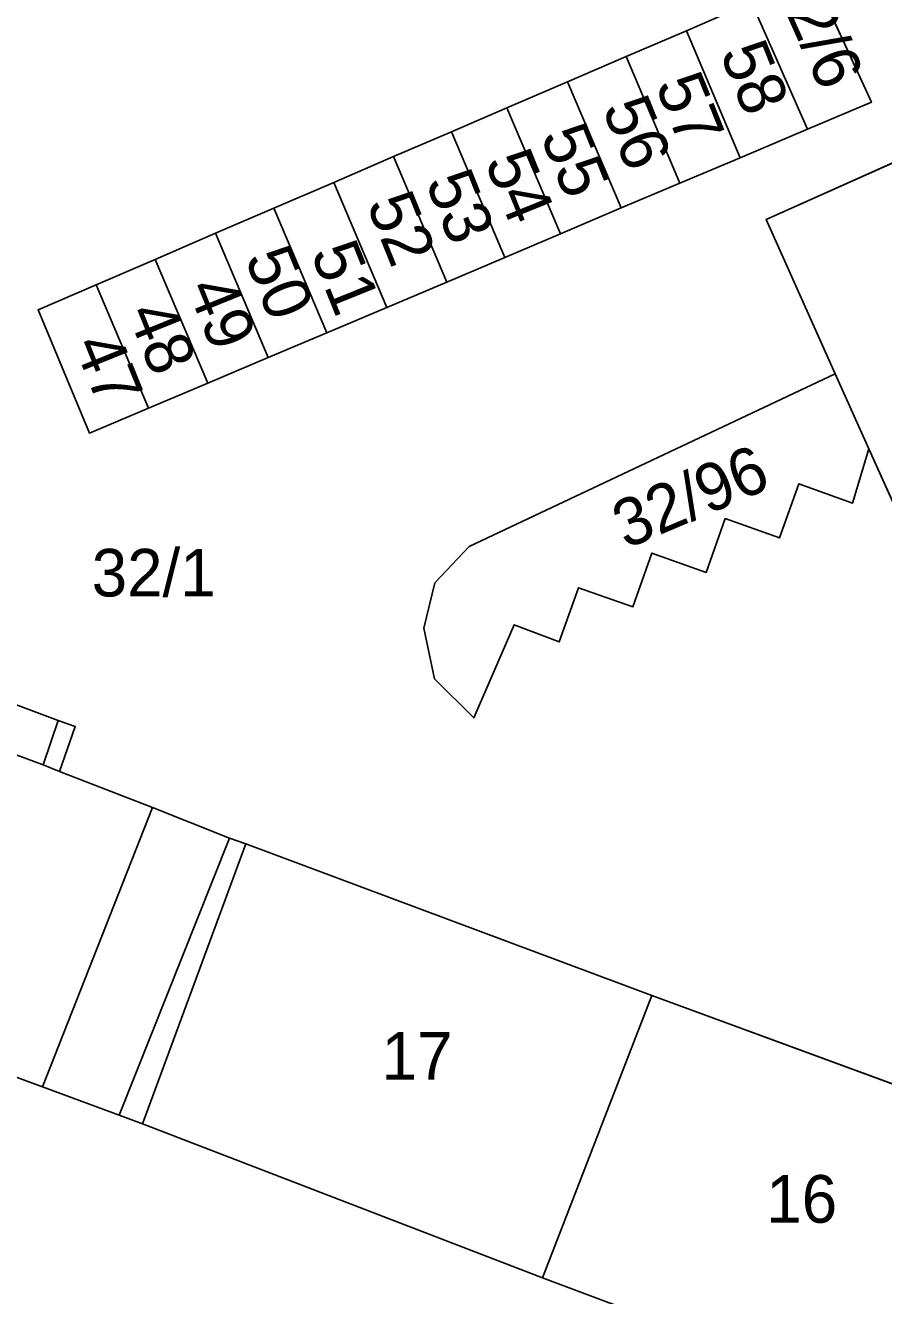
# Model space of a CAD drawing. Extents: x -264070 to -262271, y -1238894 to -1238141.
# Drawn here: x -263478.9 to -263442.9, y -1238836.1 to -1238782.8 of the extents above; entities that cross this region are included whole.
import ezdxf

# ---------------------------------------------------------------- set-up
doc = ezdxf.new("R2010")
doc.units = 0
for name, color, linetype in [('body_kn', 7, 'Continuous'), ('katuz_linie', 7, 'Continuous'), ('kladpar_druhypozemkov', 7, 'Continuous'), ('kladpar_hranice', 7, 'Continuous'), ('kladpar_parcelnecisla', 7, 'Continuous'), ('kladpar_plochy', 7, 'Continuous'), ('zappar_hrandruhpozemk', 7, 'Continuous'), ('zuob_linie', 7, 'Continuous'), ('zuob_plochy', 7, 'Continuous')]:
    doc.layers.add(name, color=color, linetype=linetype)

msp = doc.modelspace()

# ---------------------------------------------------------------- linework, layer by layer
at = {"layer": 'body_kn'}
for p, q in [((-263451.18, -1238783.03), (-263451.18, -1238783.03)), ((-263451.18, -1238783.03), (-263451.18, -1238783.03)), ((-263453.71, -1238784.11), (-263453.71, -1238784.11)), ((-263453.71, -1238784.11), (-263453.71, -1238784.11)), ((-263456.17, -1238785.17), (-263456.17, -1238785.17)), ((-263456.17, -1238785.17), (-263456.17, -1238785.17)), ((-263458.72, -1238786.27), (-263458.72, -1238786.27)), ((-263458.72, -1238786.27), (-263458.72, -1238786.27)), ((-263443.42, -1238786.03), (-263443.42, -1238786.03)), ((-263461.05, -1238787.27), (-263461.05, -1238787.27)), ((-263461.05, -1238787.27), (-263461.05, -1238787.27)), ((-263446.1, -1238787.16), (-263446.1, -1238787.16)), ((-263463.48, -1238788.31), (-263463.48, -1238788.31)), ((-263463.48, -1238788.31), (-263463.48, -1238788.31)), ((-263448.92, -1238788.36), (-263448.92, -1238788.36)), ((-263465.99, -1238789.4), (-263465.99, -1238789.4)), ((-263465.99, -1238789.4), (-263465.99, -1238789.4)), ((-263451.46, -1238789.43), (-263451.46, -1238789.43)), ((-263468.5, -1238790.48), (-263468.5, -1238790.48)), ((-263468.5, -1238790.48), (-263468.5, -1238790.48)), ((-263453.92, -1238790.47), (-263453.92, -1238790.47)), ((-263447.84, -1238790.96), (-263447.84, -1238790.96)), ((-263447.84, -1238790.96), (-263447.84, -1238790.96)), ((-263470.95, -1238791.53), (-263470.95, -1238791.53)), ((-263470.95, -1238791.53), (-263470.95, -1238791.53)), ((-263456.47, -1238791.56), (-263456.47, -1238791.56)), ((-263473.48, -1238792.63), (-263473.48, -1238792.63)), ((-263473.48, -1238792.63), (-263473.48, -1238792.63)), ((-263458.81, -1238792.55), (-263458.81, -1238792.55)), ((-263475.96, -1238793.69), (-263475.96, -1238793.69)), ((-263461.24, -1238793.58), (-263461.24, -1238793.58)), ((-263478.4, -1238794.74), (-263478.4, -1238794.74)), ((-263463.76, -1238794.65), (-263463.76, -1238794.65)), ((-263466.28, -1238795.71), (-263466.28, -1238795.71)), ((-263468.74, -1238796.75), (-263468.74, -1238796.75)), ((-263444.94, -1238797.43), (-263444.94, -1238797.43)), ((-263471.27, -1238797.83), (-263471.27, -1238797.83)), ((-263473.76, -1238798.88), (-263473.76, -1238798.88)), ((-263473.76, -1238798.88), (-263473.76, -1238798.88)), ((-263476.24, -1238799.92), (-263476.24, -1238799.92)), ((-263443.52, -1238800.58), (-263443.52, -1238800.58)), ((-263443.52, -1238800.58), (-263443.52, -1238800.58)), ((-263446.47, -1238802.05), (-263446.47, -1238802.05)), ((-263444.21, -1238802.86), (-263444.21, -1238802.86)), ((-263449.55, -1238803.51), (-263449.55, -1238803.51)), ((-263447.28, -1238804.32), (-263447.28, -1238804.32)), ((-263460.3, -1238804.68), (-263460.3, -1238804.68)), ((-263452.63, -1238804.96), (-263452.63, -1238804.96)), ((-263461.75, -1238806.21), (-263461.75, -1238806.21)), ((-263450.35, -1238805.77), (-263450.35, -1238805.77)), ((-263455.71, -1238806.41), (-263455.71, -1238806.41)), ((-263453.43, -1238807.22), (-263453.43, -1238807.22)), ((-263462.2, -1238808.11), (-263462.2, -1238808.11)), ((-263458.42, -1238807.97), (-263458.42, -1238807.97)), ((-263456.53, -1238808.69), (-263456.53, -1238808.69)), ((-263461.76, -1238810.23), (-263461.76, -1238810.23)), ((-263477.56, -1238811.99), (-263477.56, -1238811.99)), ((-263460.11, -1238811.88), (-263460.11, -1238811.88)), ((-263476.84, -1238812.24), (-263476.84, -1238812.24)), ((-263478.19, -1238813.85), (-263478.19, -1238813.85)), ((-263477.5, -1238814.12), (-263477.5, -1238814.12)), ((-263477.5, -1238814.12), (-263477.5, -1238814.12)), ((-263473.6, -1238815.64), (-263473.6, -1238815.64)), ((-263473.6, -1238815.64), (-263473.6, -1238815.64)), ((-263470.36, -1238816.92), (-263470.36, -1238816.92)), ((-263470.36, -1238816.92), (-263470.36, -1238816.92)), ((-263469.68, -1238817.17), (-263469.68, -1238817.17)), ((-263452.64, -1238823.53), (-263452.64, -1238823.53)), ((-263452.64, -1238823.53), (-263452.64, -1238823.53)), ((-263478.21, -1238827.37), (-263478.21, -1238827.37)), ((-263475, -1238828.56), (-263475, -1238828.56)), ((-263474.01, -1238828.92), (-263474.01, -1238828.92)), ((-263457.23, -1238835.39), (-263457.23, -1238835.39))]:
    msp.add_line(p, q, dxfattribs=at)
at = {"layer": 'katuz_linie'}
msp.add_lwpolyline([(-263349.05, -1238861.53), (-263351.02, -1238861.49), (-263355.33, -1238858.4), (-263357.81, -1238855.76), (-263359.53, -1238853.38), (-263363.66, -1238855.4), (-263364.29, -1238855.7), (-263364.68, -1238855.89), (-263364.91, -1238856), (-263367.96, -1238857.49), (-263381.1, -1238863.9), (-263402.68, -1238855.82), (-263419.7, -1238849.44), (-263440.2, -1238841.77), (-263457.23, -1238835.39), (-263474.01, -1238828.92), (-263475, -1238828.56), (-263478.21, -1238827.37), (-263491.85, -1238822.36), (-263508.89, -1238816.01)], dxfattribs=at)
at = {"layer": 'kladpar_druhypozemkov'}
for p, q in [((-263444.92, -1238784.28), (-263444.92, -1238784.28)), ((-263447.89, -1238784.86), (-263447.89, -1238784.86)), ((-263450.79, -1238785.75), (-263450.79, -1238785.75)), ((-263453.12, -1238787.05), (-263453.12, -1238787.05)), ((-263455.8, -1238787.9), (-263455.8, -1238787.9)), ((-263458.1, -1238789.23), (-263458.1, -1238789.23)), ((-263460.34, -1238790.14), (-263460.34, -1238790.14)), ((-263462.88, -1238791.09), (-263462.88, -1238791.09)), ((-263465.36, -1238792.48), (-263465.36, -1238792.48)), ((-263468.04, -1238793.36), (-263468.04, -1238793.36)), ((-263470.46, -1238794.51), (-263470.46, -1238794.51)), ((-263472.91, -1238795.84), (-263472.91, -1238795.84)), ((-263475.3, -1238796.58), (-263475.3, -1238796.58)), ((-263450.61, -1238801.64), (-263450.61, -1238801.64)), ((-263473.36, -1238805.31), (-263473.36, -1238805.31)), ((-263462.77, -1238825.18), (-263462.77, -1238825.18)), ((-263446.69, -1238831.06), (-263446.69, -1238831.06))]:
    msp.add_line(p, q, dxfattribs=at)
at = {"layer": 'kladpar_hranice'}
for points in [[(-263463.76, -1238794.65), (-263461.24, -1238793.58), (-263458.81, -1238792.55), (-263456.47, -1238791.56), (-263453.92, -1238790.47), (-263451.46, -1238789.43), (-263448.92, -1238788.36), (-263446.1, -1238787.16), (-263443.42, -1238786.03), (-263445.85, -1238780.73)], [(-263445.85, -1238780.73), (-263443.42, -1238786.03), (-263446.1, -1238787.16), (-263448.45, -1238781.85), (-263445.85, -1238780.73)], [(-263448.45, -1238781.85), (-263451.18, -1238783.03), (-263453.71, -1238784.11), (-263456.17, -1238785.17), (-263458.72, -1238786.27), (-263461.05, -1238787.27), (-263463.48, -1238788.31), (-263465.99, -1238789.4), (-263468.5, -1238790.48), (-263470.95, -1238791.53), (-263473.48, -1238792.63), (-263475.96, -1238793.69), (-263478.4, -1238794.74), (-263476.24, -1238799.92), (-263473.76, -1238798.88), (-263471.27, -1238797.83), (-263468.74, -1238796.75), (-263466.28, -1238795.71), (-263463.76, -1238794.65)], [(-263448.45, -1238781.85), (-263446.1, -1238787.16), (-263448.92, -1238788.36), (-263451.18, -1238783.03), (-263448.45, -1238781.85)], [(-263451.18, -1238783.03), (-263448.92, -1238788.36), (-263451.46, -1238789.43), (-263453.71, -1238784.11), (-263451.18, -1238783.03)], [(-263453.71, -1238784.11), (-263451.46, -1238789.43), (-263453.92, -1238790.47), (-263456.17, -1238785.17), (-263453.71, -1238784.11)], [(-263428.15, -1238800.21), (-263434.93, -1238785.17), (-263447.84, -1238790.96), (-263444.94, -1238797.43), (-263460.3, -1238804.68), (-263461.75, -1238806.21), (-263462.2, -1238808.11), (-263461.76, -1238810.23), (-263460.11, -1238811.88), (-263458.42, -1238807.97), (-263456.53, -1238808.69), (-263455.71, -1238806.41), (-263453.43, -1238807.22), (-263452.63, -1238804.96), (-263450.35, -1238805.77), (-263449.55, -1238803.51), (-263447.28, -1238804.32), (-263446.47, -1238802.05), (-263444.21, -1238802.86), (-263443.52, -1238800.58), (-263441.05, -1238806.08), (-263428.15, -1238800.21)], [(-263456.17, -1238785.17), (-263453.92, -1238790.47), (-263456.47, -1238791.56), (-263458.72, -1238786.27), (-263456.17, -1238785.17)], [(-263447.84, -1238790.96), (-263434.93, -1238785.17), (-263428.15, -1238800.21), (-263441.05, -1238806.08), (-263443.52, -1238800.58), (-263444.94, -1238797.43), (-263447.84, -1238790.96)], [(-263458.72, -1238786.27), (-263456.47, -1238791.56), (-263458.81, -1238792.55), (-263461.05, -1238787.27), (-263458.72, -1238786.27)], [(-263461.05, -1238787.27), (-263458.81, -1238792.55), (-263461.24, -1238793.58), (-263463.48, -1238788.31), (-263461.05, -1238787.27)], [(-263463.48, -1238788.31), (-263461.24, -1238793.58), (-263463.76, -1238794.65), (-263465.99, -1238789.4), (-263463.48, -1238788.31)], [(-263465.99, -1238789.4), (-263463.76, -1238794.65), (-263466.28, -1238795.71), (-263468.5, -1238790.48), (-263465.99, -1238789.4)], [(-263468.5, -1238790.48), (-263466.28, -1238795.71), (-263468.74, -1238796.75), (-263470.95, -1238791.53), (-263468.5, -1238790.48)], [(-263470.95, -1238791.53), (-263468.74, -1238796.75), (-263471.27, -1238797.83), (-263473.48, -1238792.63), (-263470.95, -1238791.53)], [(-263473.48, -1238792.63), (-263471.27, -1238797.83), (-263473.76, -1238798.88), (-263475.96, -1238793.69), (-263473.48, -1238792.63)], [(-263473.76, -1238798.88), (-263476.24, -1238799.92), (-263478.4, -1238794.74), (-263475.96, -1238793.69), (-263473.76, -1238798.88)], [(-263443.52, -1238800.58), (-263444.21, -1238802.86), (-263446.47, -1238802.05), (-263447.28, -1238804.32), (-263449.55, -1238803.51), (-263450.35, -1238805.77), (-263452.63, -1238804.96), (-263453.43, -1238807.22), (-263455.71, -1238806.41), (-263456.53, -1238808.69), (-263458.42, -1238807.97), (-263460.11, -1238811.88), (-263461.76, -1238810.23), (-263462.2, -1238808.11), (-263461.75, -1238806.21), (-263460.3, -1238804.68), (-263444.94, -1238797.43), (-263443.52, -1238800.58)], [(-263480.88, -1238812.87), (-263480.2, -1238810.99), (-263479.46, -1238811.27), (-263477.56, -1238811.99), (-263476.84, -1238812.24), (-263477.5, -1238814.12), (-263473.6, -1238815.64), (-263470.36, -1238816.92), (-263469.68, -1238817.17), (-263474.01, -1238828.92), (-263475, -1238828.56), (-263478.21, -1238827.37), (-263491.85, -1238822.36), (-263487.68, -1238810.28), (-263480.88, -1238812.87)], [(-263406.82, -1238831.91), (-263436.58, -1238821.21), (-263437.89, -1238825.09), (-263438.03, -1238825.49), (-263439.05, -1238828.52), (-263452.64, -1238823.53), (-263469.68, -1238817.17), (-263470.36, -1238816.92), (-263473.6, -1238815.64), (-263477.5, -1238814.12), (-263476.84, -1238812.24), (-263477.56, -1238811.99), (-263479.46, -1238811.27), (-263480.2, -1238810.99), (-263480.88, -1238812.87), (-263487.68, -1238810.28)], [(-263452.64, -1238823.53), (-263457.23, -1238835.39), (-263474.01, -1238828.92), (-263469.68, -1238817.17), (-263452.64, -1238823.53)], [(-263439.05, -1238828.52), (-263435.35, -1238829.89), (-263435.68, -1238830.82), (-263435.87, -1238831.38), (-263440.2, -1238841.77), (-263457.23, -1238835.39), (-263452.64, -1238823.53), (-263439.05, -1238828.52)]]:
    msp.add_lwpolyline(points, dxfattribs=at)
at = {"layer": 'kladpar_plochy'}
for p, q in [((-263443.42, -1238786.03), (-263445.85, -1238780.73)), ((-263448.45, -1238781.85), (-263451.18, -1238783.03)), ((-263451.18, -1238783.03), (-263453.71, -1238784.11)), ((-263453.71, -1238784.11), (-263456.17, -1238785.17)), ((-263456.17, -1238785.17), (-263458.72, -1238786.27)), ((-263434.93, -1238785.17), (-263447.84, -1238790.96)), ((-263458.72, -1238786.27), (-263461.05, -1238787.27)), ((-263446.1, -1238787.16), (-263443.42, -1238786.03)), ((-263461.05, -1238787.27), (-263463.48, -1238788.31)), ((-263448.92, -1238788.36), (-263446.1, -1238787.16)), ((-263463.48, -1238788.31), (-263465.99, -1238789.4)), ((-263451.46, -1238789.43), (-263448.92, -1238788.36)), ((-263465.99, -1238789.4), (-263468.5, -1238790.48)), ((-263453.92, -1238790.47), (-263451.46, -1238789.43)), ((-263468.5, -1238790.48), (-263470.95, -1238791.53)), ((-263456.47, -1238791.56), (-263453.92, -1238790.47)), ((-263447.84, -1238790.96), (-263444.94, -1238797.43)), ((-263470.95, -1238791.53), (-263473.48, -1238792.63)), ((-263458.81, -1238792.55), (-263456.47, -1238791.56)), ((-263473.48, -1238792.63), (-263475.96, -1238793.69)), ((-263461.24, -1238793.58), (-263458.81, -1238792.55)), ((-263475.96, -1238793.69), (-263478.4, -1238794.74)), ((-263463.76, -1238794.65), (-263461.24, -1238793.58)), ((-263478.4, -1238794.74), (-263476.24, -1238799.92)), ((-263466.28, -1238795.71), (-263463.76, -1238794.65)), ((-263468.74, -1238796.75), (-263466.28, -1238795.71)), ((-263471.27, -1238797.83), (-263468.74, -1238796.75)), ((-263444.94, -1238797.43), (-263460.3, -1238804.68)), ((-263473.76, -1238798.88), (-263471.27, -1238797.83)), ((-263476.24, -1238799.92), (-263473.76, -1238798.88)), ((-263444.21, -1238802.86), (-263443.52, -1238800.58)), ((-263443.52, -1238800.58), (-263441.05, -1238806.08)), ((-263447.28, -1238804.32), (-263446.47, -1238802.05)), ((-263446.47, -1238802.05), (-263444.21, -1238802.86)), ((-263450.35, -1238805.77), (-263449.55, -1238803.51)), ((-263449.55, -1238803.51), (-263447.28, -1238804.32)), ((-263460.3, -1238804.68), (-263461.75, -1238806.21)), ((-263453.43, -1238807.22), (-263452.63, -1238804.96)), ((-263452.63, -1238804.96), (-263450.35, -1238805.77)), ((-263461.75, -1238806.21), (-263462.2, -1238808.11)), ((-263456.53, -1238808.69), (-263455.71, -1238806.41)), ((-263455.71, -1238806.41), (-263453.43, -1238807.22)), ((-263462.2, -1238808.11), (-263461.76, -1238810.23)), ((-263460.11, -1238811.88), (-263458.42, -1238807.97)), ((-263458.42, -1238807.97), (-263456.53, -1238808.69)), ((-263461.76, -1238810.23), (-263460.11, -1238811.88)), ((-263477.56, -1238811.99), (-263479.46, -1238811.27)), ((-263476.84, -1238812.24), (-263477.56, -1238811.99)), ((-263477.5, -1238814.12), (-263476.84, -1238812.24)), ((-263473.6, -1238815.64), (-263477.5, -1238814.12)), ((-263470.36, -1238816.92), (-263473.6, -1238815.64)), ((-263469.68, -1238817.17), (-263470.36, -1238816.92)), ((-263452.64, -1238823.53), (-263469.68, -1238817.17)), ((-263439.05, -1238828.52), (-263452.64, -1238823.53))]:
    msp.add_line(p, q, dxfattribs=at)
for points in [[(-263445.85, -1238780.73), (-263443.42, -1238786.03), (-263446.1, -1238787.16), (-263448.45, -1238781.85)], [(-263448.45, -1238781.85), (-263446.1, -1238787.16), (-263448.92, -1238788.36), (-263451.18, -1238783.03)], [(-263451.18, -1238783.03), (-263448.92, -1238788.36), (-263451.46, -1238789.43), (-263453.71, -1238784.11)], [(-263453.71, -1238784.11), (-263451.46, -1238789.43), (-263453.92, -1238790.47), (-263456.17, -1238785.17)], [(-263456.17, -1238785.17), (-263453.92, -1238790.47), (-263456.47, -1238791.56), (-263458.72, -1238786.27)], [(-263447.84, -1238790.96), (-263434.93, -1238785.17), (-263428.15, -1238800.21), (-263441.05, -1238806.08), (-263443.52, -1238800.58), (-263444.94, -1238797.43)], [(-263458.72, -1238786.27), (-263456.47, -1238791.56), (-263458.81, -1238792.55), (-263461.05, -1238787.27)], [(-263461.05, -1238787.27), (-263458.81, -1238792.55), (-263461.24, -1238793.58), (-263463.48, -1238788.31)], [(-263463.48, -1238788.31), (-263461.24, -1238793.58), (-263463.76, -1238794.65), (-263465.99, -1238789.4)], [(-263465.99, -1238789.4), (-263463.76, -1238794.65), (-263466.28, -1238795.71), (-263468.5, -1238790.48)], [(-263468.5, -1238790.48), (-263466.28, -1238795.71), (-263468.74, -1238796.75), (-263470.95, -1238791.53)], [(-263470.95, -1238791.53), (-263468.74, -1238796.75), (-263471.27, -1238797.83), (-263473.48, -1238792.63)], [(-263473.48, -1238792.63), (-263471.27, -1238797.83), (-263473.76, -1238798.88), (-263475.96, -1238793.69)], [(-263473.76, -1238798.88), (-263476.24, -1238799.92), (-263478.4, -1238794.74), (-263475.96, -1238793.69)], [(-263443.52, -1238800.58), (-263444.21, -1238802.86), (-263446.47, -1238802.05), (-263447.28, -1238804.32), (-263449.55, -1238803.51), (-263450.35, -1238805.77), (-263452.63, -1238804.96), (-263453.43, -1238807.22), (-263455.71, -1238806.41), (-263456.53, -1238808.69), (-263458.42, -1238807.97), (-263460.11, -1238811.88), (-263461.76, -1238810.23), (-263462.2, -1238808.11), (-263461.75, -1238806.21), (-263460.3, -1238804.68), (-263444.94, -1238797.43)], [(-263480.88, -1238812.87), (-263480.2, -1238810.99), (-263479.46, -1238811.27), (-263477.56, -1238811.99), (-263476.84, -1238812.24), (-263477.5, -1238814.12), (-263473.6, -1238815.64), (-263470.36, -1238816.92), (-263469.68, -1238817.17), (-263474.01, -1238828.92), (-263475, -1238828.56), (-263478.21, -1238827.37), (-263491.85, -1238822.36), (-263487.68, -1238810.28)], [(-263452.64, -1238823.53), (-263457.23, -1238835.39), (-263474.01, -1238828.92), (-263469.68, -1238817.17)], [(-263439.05, -1238828.52), (-263435.35, -1238829.89), (-263435.68, -1238830.82), (-263435.87, -1238831.38), (-263440.2, -1238841.77), (-263457.23, -1238835.39), (-263452.64, -1238823.53)]]:
    msp.add_lwpolyline(points, close=True, dxfattribs=at)
at = {"layer": 'zappar_hrandruhpozemk'}
for p, q in [((-263478.19, -1238813.85), (-263477.56, -1238811.99)), ((-263477.5, -1238814.12), (-263478.19, -1238813.85)), ((-263473.6, -1238815.64), (-263478.21, -1238827.37)), ((-263470.36, -1238816.92), (-263475, -1238828.56))]:
    msp.add_line(p, q, dxfattribs=at)
msp.add_lwpolyline([(-263478.19, -1238813.85), (-263480.09, -1238813.15), (-263479.46, -1238811.27)], dxfattribs=at)
at = {"layer": 'zuob_linie'}
msp.add_lwpolyline([(-263349.05, -1238861.53), (-263351.02, -1238861.49), (-263355.33, -1238858.4), (-263357.81, -1238855.76), (-263359.53, -1238853.38), (-263363.66, -1238855.4), (-263364.29, -1238855.7), (-263364.68, -1238855.89), (-263364.91, -1238856), (-263367.96, -1238857.49), (-263381.1, -1238863.9), (-263402.68, -1238855.82), (-263419.7, -1238849.44), (-263440.2, -1238841.77), (-263457.23, -1238835.39), (-263474.01, -1238828.92), (-263475, -1238828.56), (-263478.21, -1238827.37), (-263491.85, -1238822.36), (-263508.89, -1238816.01)], dxfattribs=at)
at = {"layer": 'zuob_plochy'}
msp.add_lwpolyline([(-263349.05, -1238861.53), (-263351.02, -1238861.49), (-263355.33, -1238858.4), (-263357.81, -1238855.76), (-263359.53, -1238853.38), (-263363.66, -1238855.4), (-263364.29, -1238855.7), (-263364.68, -1238855.89), (-263364.91, -1238856), (-263367.96, -1238857.49), (-263381.1, -1238863.9), (-263402.68, -1238855.82), (-263419.7, -1238849.44), (-263440.2, -1238841.77), (-263457.23, -1238835.39), (-263474.01, -1238828.92), (-263475, -1238828.56), (-263478.21, -1238827.37), (-263491.85, -1238822.36), (-263508.89, -1238816.01)], dxfattribs=at)

# ---------------------------------------------------------------- texts
at = {"layer": 'kladpar_parcelnecisla'}
for s, rotation, p in [('32/6', 294, (-263447.633, -1238780.885)), ('58', 292, (-263449.794, -1238783.962)), ('57', 292, (-263452.508, -1238785.298)), ('56', 292, (-263454.735, -1238786.284)), ('55', 292, (-263457.326, -1238787.443)), ('54', 292, (-263459.665, -1238788.524)), ('53', 292, (-263462.154, -1238789.379)), ('52', 292, (-263464.628, -1238790.303)), ('51', 292, (-263466.972, -1238792.363)), ('50', 292, (-263469.737, -1238792.575)), ('49', 292, (-263472.155, -1238793.835)), ('48', 292, (-263474.673, -1238794.873)), ('47', 292, (-263476.917, -1238796.209)), ('32/96', 23, (-263453.721, -1238804.803))]:
    msp.add_text(s, height=2, rotation=rotation, dxfattribs=at).set_placement(p)
for s, p in [('32/1', (-263476.148, -1238806.78)), ('17', (-263463.981, -1238827.07)), ('16', (-263447.829, -1238833.07))]:
    msp.add_text(s, height=2, dxfattribs=at).set_placement(p)

doc.saveas('drawing.dxf')
